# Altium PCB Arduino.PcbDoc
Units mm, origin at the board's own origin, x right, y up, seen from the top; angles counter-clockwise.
Board outline 57.28 x 53.59 mm, 2 copper layers (Top Layer, Bottom Layer); 31 components, 27 nets, 137 pads, 34 vias.
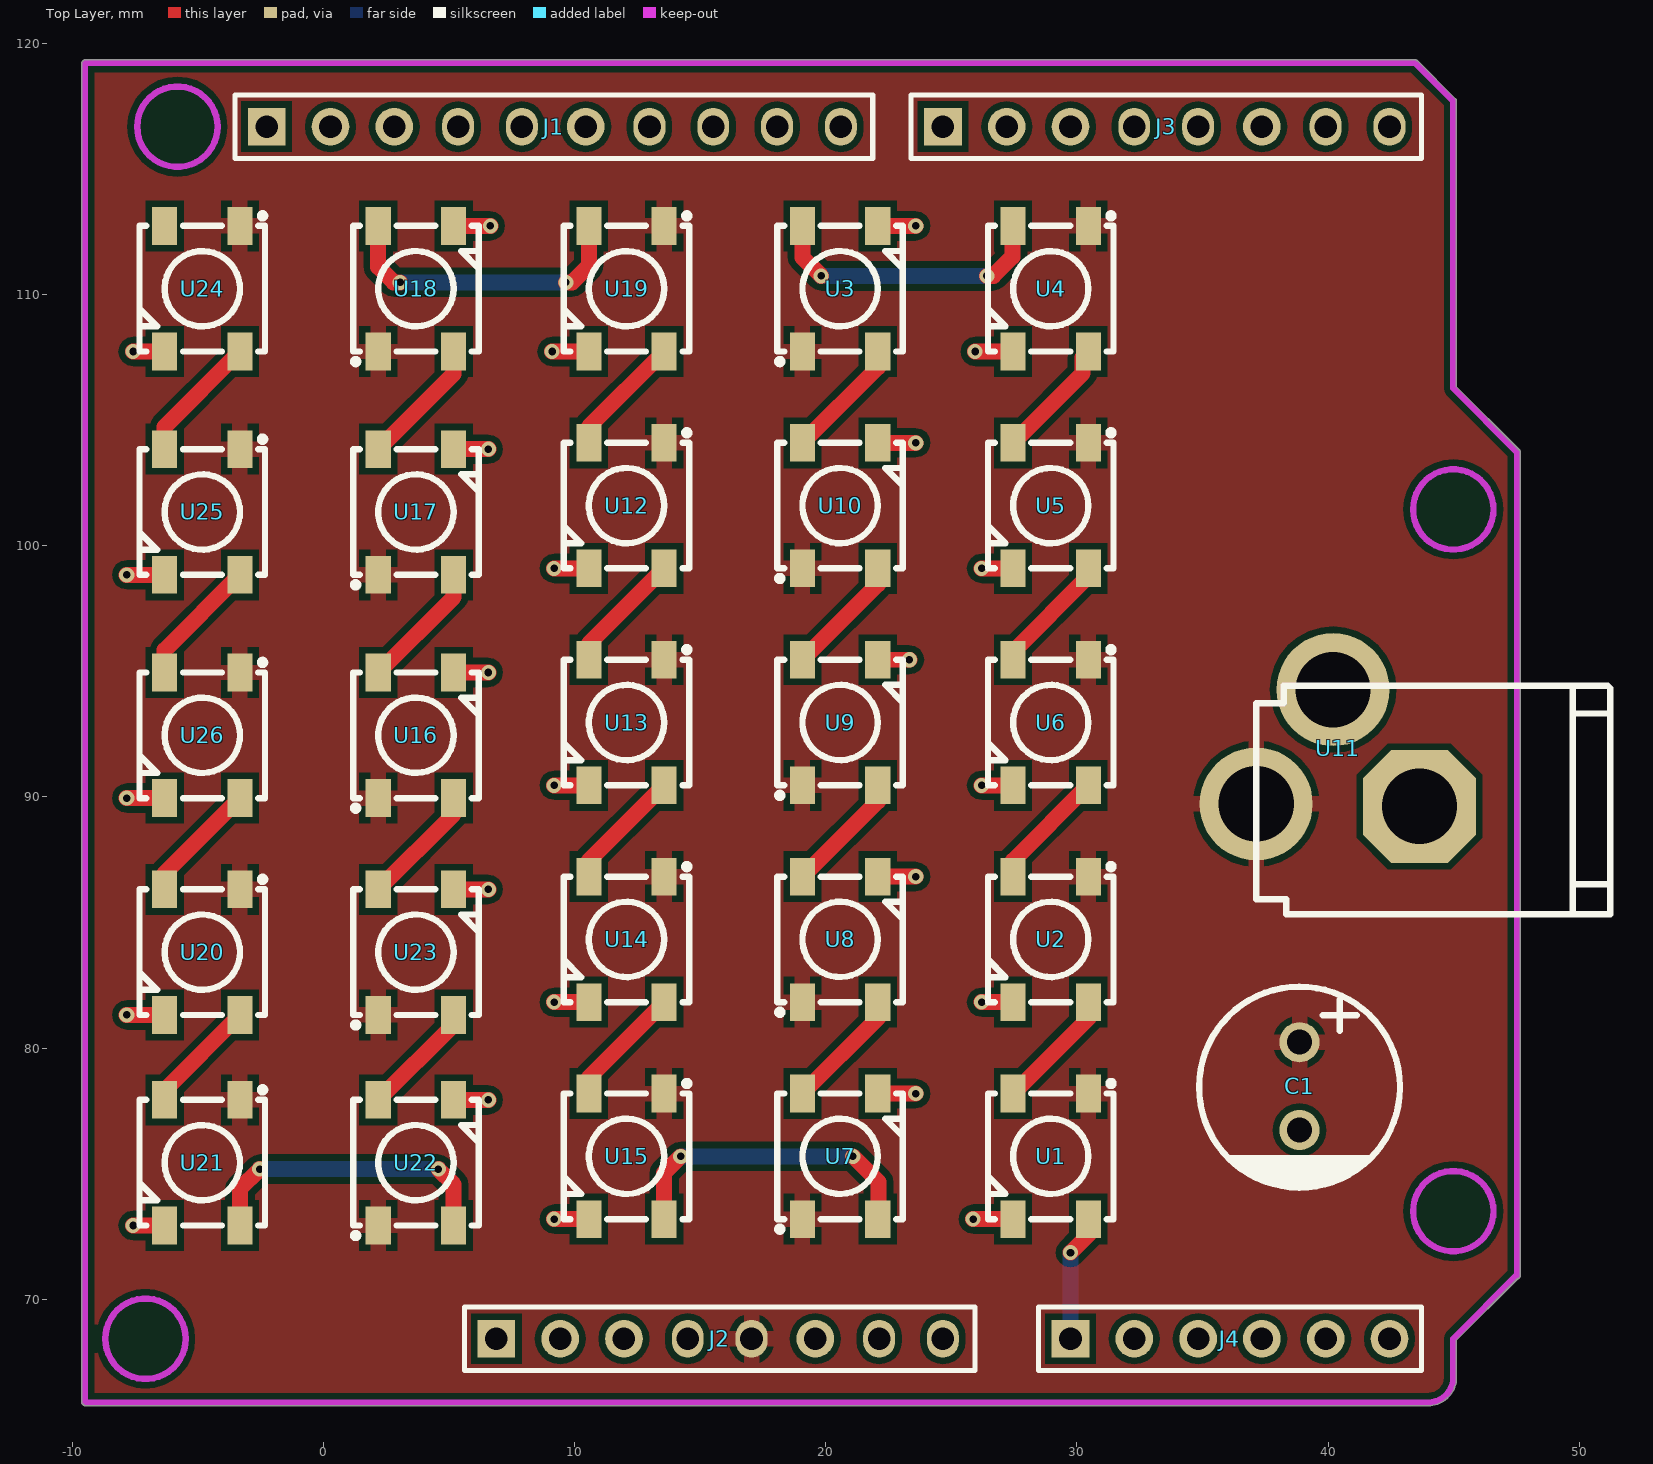
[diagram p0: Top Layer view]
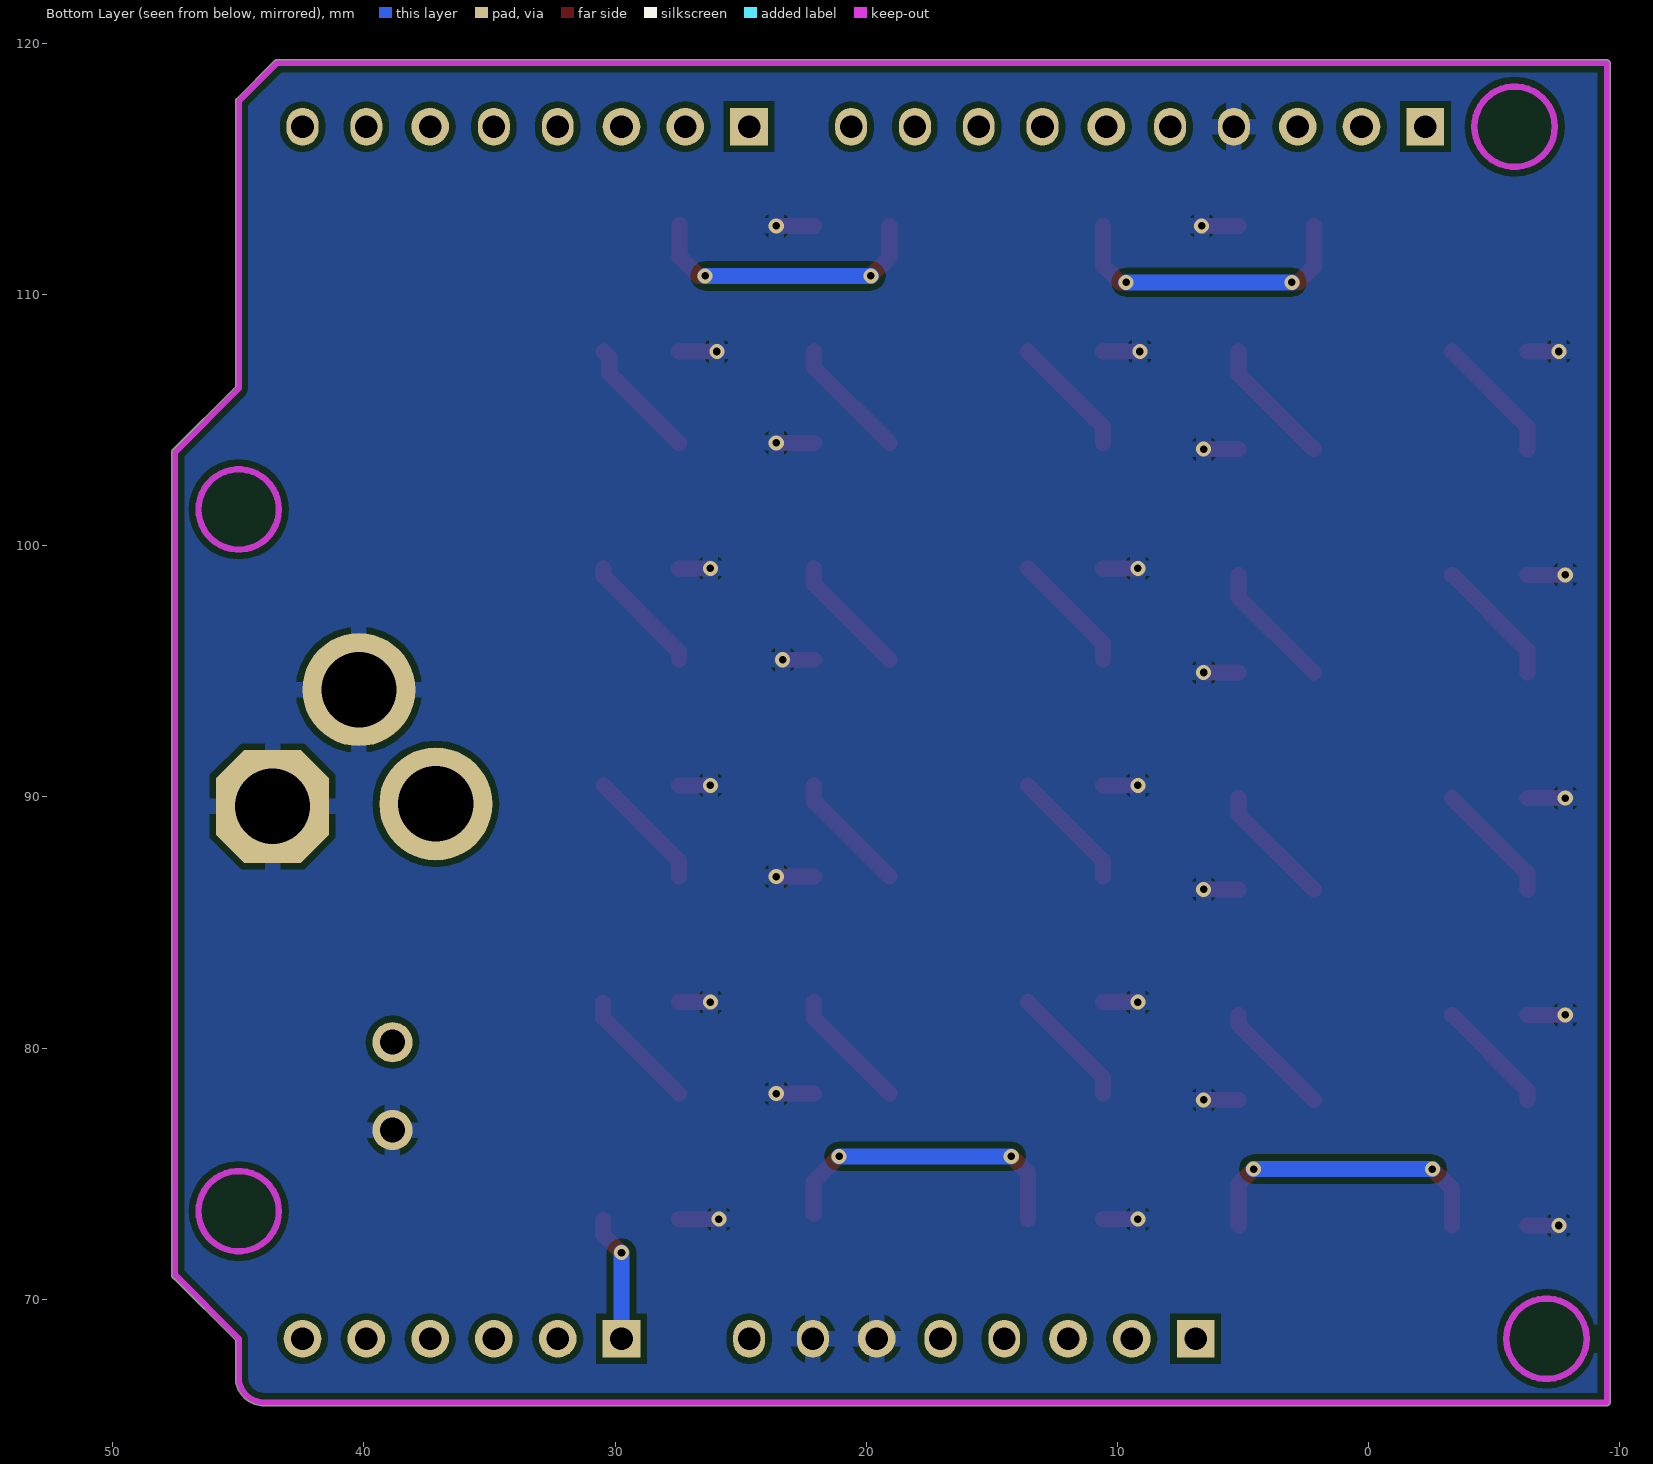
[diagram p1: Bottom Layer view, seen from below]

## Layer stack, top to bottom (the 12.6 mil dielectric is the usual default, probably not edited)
Top Layer: signal copper 0.0356
Dielectric: dielectric 0.32, FR-4, Dk 4.8
Bottom Layer: signal copper 0.0356

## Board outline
-9.627,65.913 ccw(c-9.5,65.913) -9.576,65.811 ccw(c-9.474,65.888) -9.474,65.76 43.983,65.76 ccw(c43.983,66.888) 45.111,66.888 ccw(c44.983,66.888) 45.111,66.888 45.111,68.375 47.555,70.819 ccw(c47.523,70.942) 47.651,70.942 47.651,103.734 ccw(c47.523,103.734) 47.613,103.824 45.111,106.326 45.111,117.704 ccw(c44.983,117.704) 45.073,117.794 43.549,119.318 43.55,119.317 ccw(c43.459,119.228) 43.459,119.355 -9.474,119.355 ccw(c-9.474,119.228) -9.576,119.304 ccw(c-9.5,119.202) -9.627,119.202

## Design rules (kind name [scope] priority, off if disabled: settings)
Clearance Clearance_3 [WithinRoom('CP2102')] p1: gap=0.178
Clearance [HasFootprint('QFN-28') vs InNetClass('All Nets')] p2: gap=0.178
Clearance Clearance_2 [All] p3: gap=0.254
Clearance Clearance_1 [All] p4: gap=0.254
HoleSize [All] p1: absolutevalues=TRUE maxlimit=3 minlimit=0.025 maxpercent=80.000 minpercent=20.000
HoleToHoleClearance [All] p1: gap=0 allowstackedmicrovias=TRUE
MinimumSolderMaskSliver [All] p1: minsoldermaskwidth=0
PolygonConnect [All] p1: connectstyle=Relief reliefconductorwidth=0.635 reliefentries=4 polygonreliefangle="90 Angle"
RoutingVias [All] p1: holewidth=0.2 width=1.27 viastyle="Through Hole" minholewidth=0.2 minwidth=0.2 maxholewidth=1.2 maxwidth=1.27
SilkToSilkClearance [All] p1: silktosilkclearance=0
SilkscreenOverComponentPads [All] p1: minsilkscreentomaskgap=0
SolderMaskExpansion [All] p1: expansion=0.102
Width [All] p1: maxlimit=6 minlimit=0.254 preferedwidth=0.254
23 further rules are at their usual default settings.

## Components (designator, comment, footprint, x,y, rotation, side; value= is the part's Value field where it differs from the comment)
C1 "Cap Pol" CAP-TH_BD8.0-P3.50-D1.0-FD 38.862,78.486 r270 top
J1 "CON10" HDR1X10Z -2.261,116.688 r0 top
J2 "CON8" HDR1X8Z 6.883,68.428 r0 top
J3 "CON8" HDR1X8Z 24.663,116.688 r0 top
J4 "CON6" HDR1X6Z 29.743,68.428 r0 top
U1 "WS2812B" LED-SMD_4P-L5.0-W5.0-TL 28.956,75.692 r270 top
U2 "WS2812B" LED-SMD_4P-L5.0-W5.0-TL 28.956,84.328 r270 top
U3 "WS2812B" LED-SMD_4P-L5.0-W5.0-TL 20.571,110.236 r90 top
U4 "WS2812B" LED-SMD_4P-L5.0-W5.0-TL 28.956,110.236 r270 top
U5 "WS2812B" LED-SMD_4P-L5.0-W5.0-TL 28.956,101.6 r270 top
U6 "WS2812B" LED-SMD_4P-L5.0-W5.0-TL 28.956,92.964 r270 top
U7 "WS2812B" LED-SMD_4P-L5.0-W5.0-TL 20.571,75.692 r90 top
U8 "WS2812B" LED-SMD_4P-L5.0-W5.0-TL 20.571,84.328 r90 top
U9 "WS2812B" LED-SMD_4P-L5.0-W5.0-TL 20.571,92.964 r90 top
U10 "WS2812B" LED-SMD_4P-L5.0-W5.0-TL 20.571,101.6 r90 top
U11 "VCCIN" VCCIN 40.386,91.948 r180 top
U12 "WS2812B" LED-SMD_4P-L5.0-W5.0-TL 12.065,101.6 r270 top
U13 "WS2812B" LED-SMD_4P-L5.0-W5.0-TL 12.065,92.964 r270 top
U14 "WS2812B" LED-SMD_4P-L5.0-W5.0-TL 12.065,84.328 r270 top
U15 "WS2812B" LED-SMD_4P-L5.0-W5.0-TL 12.065,75.692 r270 top
U16 "WS2812B" LED-SMD_4P-L5.0-W5.0-TL 3.68,92.456 r90 top
U17 "WS2812B" LED-SMD_4P-L5.0-W5.0-TL 3.68,101.346 r90 top
U18 "WS2812B" LED-SMD_4P-L5.0-W5.0-TL 3.68,110.236 r90 top
U19 "WS2812B" LED-SMD_4P-L5.0-W5.0-TL 12.065,110.236 r270 top
U20 "WS2812B" LED-SMD_4P-L5.0-W5.0-TL -4.826,83.82 r270 top
U21 "WS2812B" LED-SMD_4P-L5.0-W5.0-TL -4.826,75.438 r270 top
U22 "WS2812B" LED-SMD_4P-L5.0-W5.0-TL 3.68,75.438 r90 top
U23 "WS2812B" LED-SMD_4P-L5.0-W5.0-TL 3.68,83.82 r90 top
U24 "WS2812B" LED-SMD_4P-L5.0-W5.0-TL -4.826,110.236 r270 top
U25 "WS2812B" LED-SMD_4P-L5.0-W5.0-TL -4.826,101.346 r270 top
U26 "WS2812B" LED-SMD_4P-L5.0-W5.0-TL -4.826,92.456 r270 top

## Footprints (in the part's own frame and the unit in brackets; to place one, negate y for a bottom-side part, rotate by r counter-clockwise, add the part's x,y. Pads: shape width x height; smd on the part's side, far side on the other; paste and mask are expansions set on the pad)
CAP-TH_BD8.0-P3.50-D1.0-FD [mm]
  round 1.6 hole 1: 1(-1.75,0) 2(1.75,0)
  silkscreen extent -3.96,-4 4.04,4
HDR1X6Z [mm]
  rect 1.5x1.5 hole 0.9: 1(0,0)
  round 1.5 hole 0.9: 2(2.54,0) 3(5.08,0) 4(7.62,0) 5(10.16,0) 6(12.7,0)
  silkscreen extent -1.27,-1.27 13.97,1.27
HDR1X8Z [mm]
  rect 1.5x1.5 hole 0.9: 1(0,0)
  round 1.5 hole 0.9: 2(2.54,0) 3(5.08,0) 6(12.7,0)
  oval 1.27x1.5 hole 0.9: 4(7.62,0) 5(10.16,0) 7(15.24,0) 8(17.78,0)
  silkscreen extent -1.27,-1.27 19.05,1.27
HDR1X10Z [mm] "Connector; He"
  rect 1.5x1.5 hole 0.9: 1(0,0)
  round 1.5 hole 0.9: 2(2.54,0) 3(5.08,0) 6(12.7,0)
  oval 1.27x1.5 hole 0.9: 4(7.62,0) 5(10.16,0) 7(15.24,0) 8(17.78,0) 9(20.32,0) 10(22.86,0)
  silkscreen extent -1.27,-1.27 24.13,1.27
LED-SMD_4P-L5.0-W5.0-TL [mm]
  rect 1.5x1 smd: 1(-2.5,1.5) 2(-2.5,-1.5) 3(2.5,-1.5) 4(2.5,1.5)
  silkscreen extent -3,-2.5 2.5,2.5
VCCIN [mm]
  oct 4.5x4.5 hole 3: 1(-3.25,2.324)
  round 4.5 hole 3: 2(3.25,2.224) 3(0.19,-2.324)
  silkscreen extent -10.85,-2.48 3.25,6.62

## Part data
C1: "Polarized Capacitor"
J1 J2 J3: "Connector"
J4: "C"

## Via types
v1: diameter 0.6, hole 0.3, Top Layer to Bottom Layer, 34 vias

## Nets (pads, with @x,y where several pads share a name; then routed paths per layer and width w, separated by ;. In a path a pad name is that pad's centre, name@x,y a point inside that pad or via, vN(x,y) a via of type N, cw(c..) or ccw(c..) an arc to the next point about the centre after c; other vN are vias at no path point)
+5V: C1.1 J2.5 U1.1 U2.1 U3.1 U4.1 U5.1 U6.1 U7.1 U8.1 U9.1 U10.1 U11.2 U12.1 U13.1 U14.1 U15.1 U16.1 U17.1 U18.1 U19.1 U20.1 U21.1 U22.1 U23.1 U24.1 U25.1 U26.1
A0: J4.1 U1.4 | length 5
  Top Layer w0.635: v1(29.743,71.857) 30.48,72.593 U1.4@30.48,73.152
  Bottom Layer w0.635: J4.1 v1(29.743,71.857)
GND: C1.2 J1.4 J2.6 J2.7 U1.3 U2.3 U3.3 U4.3 U5.3 U6.3 U7.3 U8.3 U9.3 U10.3 U11.1 U11.3 U12.3 U13.3 U14.3 U15.3 U16.3 U17.3 U18.3 U19.3 U20.3 U21.3 U22.3 U23.3 U24.3 U25.3 U26.3 | length 35.2
  Top Layer w0.635: v1(-7.834,81.32) U20.3 ; v1(-7.834,89.956) U26.3 ; v1(-7.834,98.846) U25.3 ; v1(-7.58,72.938) U21.3 ; v1(-7.58,107.736) U24.3 ; U22.3 v1(6.564,77.938) ; U23.3 v1(6.564,86.32) ; U16.3 v1(6.564,94.956) ; U17.3 v1(6.564,103.846) ; U18.3 v1(6.644,112.736) ; v1(9.104,107.736) U19.3 ; v1(9.184,73.192) U15.3 ; v1(9.184,81.828) U14.3 ; v1(9.184,90.464) U13.3 ; v1(9.184,99.1) U12.3 ; U7.3 v1(23.582,78.192) ; U8.3 v1(23.582,86.828) ; U9.3 v1(23.328,95.464) ; U10.3 v1(23.582,104.1) ; U3.3 v1(23.582,112.736) ; v1(25.868,73.192) U1.3 ; v1(25.948,107.736) U4.3 ; v1(26.202,90.464) U6.3 ; v1(26.202,81.828) U2.3 ; v1(26.202,99.1) U5.3
NetU1_2: U1.2 U2.4 | length 4.8
  Top Layer w0.635: U1.2 30.48,81.216 U2.4@30.48,81.788
NetU2_2: U2.2 U6.4 | length 4.9
  Top Layer w0.635: U2.2 27.456,87.464 U6.4
NetU3_2: U3.2 U10.4 | length 4.9
  Top Layer w0.635: U10.4 22.07,107.1 U3.2
NetU3_4: U3.4 U4.2 | length 11.5
  Top Layer w0.635: U3.4 19.071,111.485 v1(19.812,110.744) ; v1(26.416,110.744) 26.67,110.744 27.432,111.506 U4.2@27.432,112.776
  Bottom Layer w0.635: v1(19.812,110.744) v1(26.416,110.744)
NetU4_4: U4.4 U5.2 | length 4.9
  Top Layer w0.635: U5.2 30.226,106.87 30.226,107.506 U4.4
NetU5_4: U5.4 U6.2 | length 4.9
  Top Layer w0.635: U6.2 27.456,95.782 30.456,98.782 U5.4
NetU7_2: U7.2 U15.4 | length 12.3
  Top Layer w0.635: U15.4 13.565,75.033 v1(14.224,75.692) ; v1(21.082,75.692) 22.098,74.676 U7.2@22.098,73.406
  Bottom Layer w0.635: v1(14.224,75.692) v1(21.082,75.692)
NetU7_4: U7.4 U8.2 | length 4.9
  Top Layer w0.635: U7.4 22.07,81.192 U8.2
NetU8_4: U8.4 U9.2 | length 4.9
  Top Layer w0.635: U8.4 22.07,89.828 U9.2
NetU9_4: U9.4 U10.2 | length 4.9
  Top Layer w0.635: U9.4 22.07,98.464 U10.2
NetU12_2: U12.2 U19.4 | length 4.9
  Top Layer w0.635: U12.2 10.565,104.736 U19.4
NetU12_4: U12.4 U13.2 | length 4.9
  Top Layer w0.635: U13.2 10.565,96.1 U12.4
NetU13_4: U13.4 U14.2 | length 4.9
  Top Layer w0.635: U14.2 10.565,87.464 U13.4
NetU14_4: U14.4 U15.2 | length 4.9
  Top Layer w0.635: U15.2 10.565,78.828 U14.4
NetU16_2: U16.2 U23.4 | length 4.9
  Top Layer w0.635: U23.4 5.179,89.32 U16.2
NetU16_4: U16.4 U17.2 | length 5.1
  Top Layer w0.635: U16.4 5.179,97.956 U17.2
NetU17_4: U17.4 U18.2 | length 5.1
  Top Layer w0.635: U17.4 5.179,106.846 U18.2
NetU18_4: U18.4 U19.2 | length 12.1
  Top Layer w0.635: U18.4 2.18,111.104 2.794,110.49 v1(3.048,110.49) ; v1(9.652,110.49) 9.906,110.49 10.565,111.149 U19.2
  Bottom Layer w0.635: v1(3.048,110.49) v1(9.652,110.49)
NetU20_2: U20.2 U26.4 | length 4.9
  Top Layer w0.635: U20.2 -6.326,86.956 U26.4
NetU20_4: U20.4 U21.2 | length 4.6
  Top Layer w0.635: U21.2 -6.326,78.32 U20.4
NetU21_4: U21.4 U22.2 | length 12.2
  Top Layer w0.635: U21.4 -3.326,74.398 v1(-2.54,75.184) ; v1(4.572,75.184) 5.179,74.577 U22.2
  Bottom Layer w0.635: v1(-2.54,75.184) v1(4.572,75.184)
NetU22_4: U22.4 U23.2 | length 4.6
  Top Layer w0.635: U22.4 5.179,80.938 U23.2
NetU24_4: U24.4 U25.2 | length 5.1
  Top Layer w0.635: U25.2 -6.326,104.736 U24.4
NetU25_4: U25.4 U26.2 | length 5.1
  Top Layer w0.635: U26.2 -6.326,95.846 U25.4
pads on no net: J1.1 J1.2 J1.3 J1.5 J1.6 J1.7 J1.8 J1.9 J1.10 J2.1 J2.2 J2.3 J2.4 J2.8 J3.1 J3.2 J3.3 J3.4 J3.5 J3.6 J3.7 J3.8 J4.2 J4.3 J4.4 J4.5 J4.6 U24.2

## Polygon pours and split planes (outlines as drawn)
+5V on Top Layer "Keep-Out Layer-No Net" (solid, remove dead copper): -9.627,65.913 ccw(c-9.5,65.913) -9.576,65.811 ccw(c-9.474,65.888) -9.474,65.76 43.983,65.76 ccw(c43.983,66.888) 45.111,66.888 ccw(c44.983,66.888) 45.111,66.888 45.111,68.375 47.555,70.819 ccw(c47.523,70.942) 47.651,70.942 47.651,103.734 ccw(c47.523,103.734) 47.613,103.824 45.111,106.326 45.111,117.704 ccw(c44.983,117.704) 45.073,117.794 43.549,119.318 43.55,119.317 ccw(c43.459,119.228) 43.459,119.355 -9.474,119.355 ccw(c-9.474,119.228) -9.576,119.304 ccw(c-9.5,119.202) -9.627,119.202
GND on Bottom Layer "Keep-Out Layer-No Net" (solid, remove dead copper): -9.627,65.913 ccw(c-9.5,65.913) -9.576,65.811 ccw(c-9.474,65.888) -9.474,65.76 43.983,65.76 ccw(c43.983,66.888) 45.111,66.888 ccw(c44.983,66.888) 45.111,66.888 45.111,68.375 47.555,70.819 ccw(c47.523,70.942) 47.651,70.942 47.651,103.734 ccw(c47.523,103.734) 47.613,103.824 45.111,106.326 45.111,117.704 ccw(c44.983,117.704) 45.073,117.794 43.549,119.318 43.55,119.317 ccw(c43.459,119.228) 43.459,119.355 -9.474,119.355 ccw(c-9.474,119.228) -9.576,119.304 ccw(c-9.5,119.202) -9.627,119.202

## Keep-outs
Keep-Out Layer:
  circle w0.254: c44.983,101.448 r1.6
  circle w0.254: c-7.087,68.428 r1.6
  circle w0.254: c-5.817,116.688 r1.6
  circle w0.254: c44.983,73.508 r1.6
  lines w0.254: -9.5,65.888 -9.5,119.202 -9.474,119.228 43.459,119.228 44.983,117.704 44.983,106.274 47.523,103.734 47.523,103.657 47.523,80.772 47.523,70.968 44.983,68.428 44.983,66.888 cw(c43.983,66.888) 43.983,65.888 -9.5,65.888

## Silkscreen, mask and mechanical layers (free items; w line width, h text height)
Mechanical 1:
  circle w0.254: c44.983,101.448 r1.6
  circle w0.254: c-7.087,68.428 r1.6
  circle w0.254: c-5.817,116.688 r1.6
  circle w0.254: c44.983,73.508 r1.6
  lines w0.254: -9.5,65.913 -9.5,119.202 ; -9.474,65.888 43.983,65.888 ccw(c43.983,66.888) 44.983,66.888 44.983,68.428 47.523,70.968 ; -9.474,119.228 43.459,119.228 44.983,117.704 44.983,106.274 47.523,103.734 47.523,70.942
